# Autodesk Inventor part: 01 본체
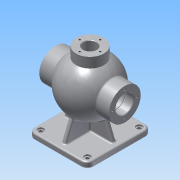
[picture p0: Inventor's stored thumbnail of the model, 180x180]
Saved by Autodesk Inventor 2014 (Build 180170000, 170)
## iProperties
Created: 2017-01
Part Number: 01 본체
Material: Aluminum 6061
Document SubType Name: Modeling
Designer: ksu
Density: 2.71 g/cm^3
Appearance: Aluminum - Flat
Author: ksu
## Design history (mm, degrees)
sketch "Sketch1"
  geometry: L1 (0, 0)-(20.642, 0); L2 (99.745, 0)-(136, 0); L3 (0, 0)-(136, 0); L4 (0, 0)-(136, 0); L5 (136, 0)-(136, 31); L6 (0, 31)-(0, 0); L7 (136, 31)-(110.741, 31); L8 (25.012, 31)-(0, 31); A1 r 53 centre (67.876, -0.171) between (110.741, 31) and (25.012, 31)
  constraints: 16 end point, 3 horizontal, 3 parallel, 2 point on circle, 1 centre point, 1 collinear, 1 perpendicular
  dimensions: "d2" = 136 distance between parallel lines of L6 L5; "d40" = 31 distance between parallel lines of L1 L8; "d41" = 31 distance between parallel lines of L2 L7
revolve "Revolution1" sketch "Sketch1" stored, may be unused: angle "d3" = 90 deg
workplane "Work Plane1"
sketch "Sketch2"
  geometry: L1 (0, 31)-(0, -31) reference; L2 (-136, 31)-(-136, -31) reference; L3 (-110.741, 31)-(-136, 31) reference; L4 (-22.5, 62.5)-(-113.5, 62.5); L5 (-125.5, 50.5)-(-125.5, -50.5); L6 (-113.5, -62.5)-(-22.5, -62.5); L7 (-10.5, -50.5)-(-10.5, 50.5); A1 r 12 centre (-22.5, 50.5) between (-10.5, 50.5) and (-22.5, 62.5); A2 r 12 centre (-22.5, -50.5) between (-22.5, -62.5) and (-10.5, -50.5); A3 r 12 centre (-113.5, -50.5) between (-125.5, -50.5) and (-113.5, -62.5); A4 r 12 centre (-113.5, 50.5) between (-113.5, 62.5) and (-125.5, 50.5); 4 further points
  constraints: 8 end point, 8 point on circle, 8 tangent, 6 point on line, 4 centre point, 3 equal radius, 2 parallel, 1 horizontal, 1 perpendicular
  dimensions: "d10" = 115 distance of point (-10.5, -62.5) point (-125.5, -62.5); "d11" = 125 distance of point (-125.5, -62.5) point (-125.5, 62.5); "d12" = 12 radius of A1
extrude "Extrusion1" join sketch "Sketch2" distance "d13" = 10; taper "d14" = 0 deg
sketch "Sketch3"
  geometry: A1 r 12 centre (113.5, -50.5) between (113.5, -62.5) and (125.5, -50.5) reference; A2 r 12 centre (113.5, 50.5) between (125.5, 50.5) and (113.5, 62.5) reference; A3 r 12 centre (22.5, 50.5) between (22.5, 62.5) and (10.5, 50.5) reference; A4 r 12 centre (22.5, -50.5) between (10.5, -50.5) and (22.5, -62.5) reference; 5 further points
  constraints: 4 coincident
hole "Hole1" sketch "Sketch3" at (22.5, -50.5), (22.5, 50.5), (113.5, 50.5), (113.5, -50.5) diameter "d15" = 8; stored, may be unused: countersink angle "d19" = 90 deg, drill point angle "d21" = 0 deg; dims "d16" = 6, "d17" = 12, "d18" = 3, "d20" = 10
workplane "Work Plane2"
workplane "Work Plane3"
workplane "Work Plane4"
sketch "Sketch11"
  geometry: L1 (0, -31)-(0, 31) reference; L2 (0, 31)-(25.012, 31) reference; L3 (110.741, 31)-(136, 31) reference; L4 (136, 31)-(136, -31) reference; L5 (136, -31)-(110.741, -31) reference; L6 (25.012, -31)-(0, -31) reference; L7 (10.5, -75)-(125.5, -75) reference; L8 (125.5, -75)-(125.5, -85) reference; L9 (125.5, -85)-(10.5, -85) reference; L10 (10.5, -85)-(10.5, -75) reference; L11 (0, 0)-(136, 0); L12 (136, 0)-(136, 17.5); L13 (0, 17.5)-(0, 0); L14 (28.523, 17.5)-(0, 17.5); L15 (120, 0)-(118.25, 0); L16 (118.25, 17.5)-(118.25, 18.5); L17 (118.25, 18.5)-(120, 18.5); L18 (120, 18.5)-(120, 17.5); L19 (136, 17.5)-(120, 17.5); L20 (118.25, 17.5)-(107.23, 17.5); A1 r 43 centre (67.876, 0.171) between (107.23, 17.5) and (28.523, 17.5); A2 r 53 centre (67.876, 0.171) between (25.012, -31) and (110.741, -31) reference; A3 r 53 centre (67.876, -0.171) between (110.741, 31) and (25.012, 31) reference
  constraints: 20 end point, 6 parallel, 2 horizontal, 2 perpendicular, 2 point on circle, 2 point on line, 1 centre point
  dimensions: "d75" = 86 diameter of A1; "d77" = 1.75 distance of L16.end L17.end; "d78" = 16 distance between parallel lines of L4 L18; "d79" = 18.5 distance of L17.end L15.start
revolve "Revolution2" sketch "Sketch11" stored, may be unused: angle "d80" = 90 deg
sketch "Sketch12"
  geometry: C1 r 17.5 at (0, 0) reference; 4 further points
  constraints: 5 other
  dimensions: "d81" = 24 distance of C1.centre point (0, 24); "d84" = 360 deg dimension on C1.centre point (0, 24) (derived)
hole "Hole2" sketch "Sketch12" at (0, 24), (-24, 0), (0, -24), (24, 0) diameter "d86" = 3.459; stored, may be unused: countersink angle "d90" = 90 deg, drill point angle "d92" = 118 deg; dims "d87" = 16, "d88" = 12, "d89" = 3, "d91" = 19
sketch "Sketch13"
  geometry: C1 r 17.5 at (0, 0) reference; 4 further points
  constraints: 5 other
  dimensions: "d93" = 22.5 distance of C1.centre point (0, 22.5); "d96" = 360 deg dimension on C1.centre point (0, 22.5) (derived)
hole "Hole3" sketch "Sketch13" at (0, 22.5), (-22.5, 0), (0, -22.5), (22.5, 0) diameter "d98" = 3.459; stored, may be unused: countersink angle "d102" = 90 deg, drill point angle "d104" = 118 deg; dims "d99" = 12, "d100" = 12, "d101" = 3, "d103" = 15
chamfer "Chamfer1" distance "d120" = 1; stored, may be unused: second distance "d121" = 2, angle "d122" = 45 deg
fillet "Fillet1" dims "d123" = 3
fillet "Fillet3" dims "d125" = 3
sketch "Sketch16"
  geometry: L1 (16.039, 22.5)-(15, 24.23) reference; L2 (0, 20.77)-(15, 20.77) reference; L3 (0, 24.23)-(0, 31) reference; L4 (0, 31)-(23.51, 31) reference; L5 (28.523, 17.5)-(1, 17.5) reference; L6 (1, 17.5)-(0, 18.5) reference; L7 (0, 18.5)-(0, 20.77) reference; L8 (15, 24.23)-(0, 24.23) reference; L9 (15, 20.77)-(16.039, 22.5) reference; L10 (117, -22.271)-(115.961, -24) reference; L11 (115.961, -24)-(117, -25.73) reference; L12 (117, -25.73)-(136, -25.73) reference; L13 (136, -25.73)-(136, -31) reference; L14 (136, -31)-(112.242, -31) reference; L15 (23.51, -31)-(0, -31) reference; L16 (0, -31)-(0, -24.23) reference; L17 (0, -24.23)-(15, -24.23) reference; L18 (15, -24.23)-(16.039, -22.5) reference; L19 (16.039, -22.5)-(15, -20.77) reference; L20 (15, -20.77)-(0, -20.77) reference; L21 (0, -20.77)-(0, -18.5) reference; L22 (0, -18.5)-(1, -17.5) reference; L23 (1, -17.5)-(28.523, -17.5) reference; L24 (107.23, -17.5)-(118.25, -17.5) reference; L25 (118.25, -17.5)-(118.25, -18.5) reference; L26 (118.25, -18.5)-(120, -18.5) reference; L27 (120, -18.5)-(120, -17.5) reference; L28 (120, -17.5)-(135, -17.5) reference; L29 (135, -17.5)-(136, -18.5) reference; L30 (136, -18.5)-(136, -22.271) reference; L31 (136, -22.271)-(117, -22.271) reference; L32 (117, 25.73)-(115.961, 24) reference; L33 (115.961, 24)-(117, 22.271) reference; L34 (117, 22.271)-(136, 22.271) reference; L35 (136, 22.271)-(136, 18.5) reference; L36 (136, 18.5)-(135, 17.5) reference; L37 (135, 17.5)-(120, 17.5) reference; L38 (120, 17.5)-(120, 18.5) reference; L39 (120, 18.5)-(118.25, 18.5) reference; L40 (118.25, 18.5)-(118.25, 17.5) reference; L41 (118.25, 17.5)-(107.23, 17.5) reference; L42 (112.242, 31)-(136, 31) reference; L43 (136, 31)-(136, 25.73) reference; L44 (136, 25.73)-(117, 25.73) reference; L45 (125.5, -78)-(125.5, -85) reference; L46 (125.5, -85)-(10.5, -85) reference; L47 (10.5, -85)-(10.5, -78) reference; L48 (13.5, -75)-(122.5, -75) reference; L49 (20.5, -75)-(36.603, -35.143); L50 (115.5, -75)-(99.331, -34.98); L51 (115.5, -75)-(20.5, -75); A1 r 3 centre (23.51, 34) between (23.51, 31) and (25.887, 32.169) reference; A2 r 43 centre (67.876, 0.171) between (107.23, 17.5) and (28.523, 17.5) reference; A3 r 3 centre (112.242, -34) between (112.242, -31) and (109.866, -32.169) reference; A4 r 53 centre (67.876, 0.171) between (25.887, -32.169) and (109.866, -32.169) reference; A5 r 3 centre (23.51, -34) between (25.887, -32.169) and (23.51, -31) reference; A6 r 43 centre (67.876, -0.171) between (28.523, -17.5) and (107.23, -17.5) reference; A7 r 3 centre (112.242, 34) between (109.866, 32.169) and (112.242, 31) reference; A8 r 3 centre (122.5, -78) between (125.5, -78) and (122.5, -75) reference; A9 r 3 centre (13.5, -78) between (13.5, -75) and (10.5, -78) reference; A10 r 46.916 centre (67.876, -0.171) between (36.603, -35.143) and (99.331, -34.98); A11 r 53 centre (67.876, -0.171) between (109.866, 32.169) and (25.887, 32.169) reference; 1 further point
  constraints: 6 end point, 2 point on circle, 2 point on line, 1 centre point, 1 collinear
  dimensions: "d126" = 22 deg angle of L47 L49; "d127" = 22 deg angle of L45 L50; "d128" = 10 distance from line of L45 L50.start; "d129" = 10 distance from line of L47 L49.start
extrude "Extrusion7" join sketch "Sketch16" distance "d130" = 4; taper "d132" = 0 deg; dims "d131" = 4, "d133" = 0
workplane "Work Plane5"
sketch "Sketch17"
  geometry: L1 (-52.677, -4)-(-75, -4) reference; L2 (-75, -4)-(-75, -59.5) reference; L3 (-78, -62.5)-(-85, -62.5) reference; L4 (-85, -62.5)-(-85, 62.5) reference; L5 (-85, 62.5)-(-78, 62.5) reference; L6 (-75, 59.5)-(-75, 4) reference; L7 (-75, 4)-(-52.677, 4) reference; L8 (-75, 52.5)-(-32.266, 35.234); L9 (-75, -52.5)-(-32.266, -35.234); L10 (-75, 52.5)-(-75, -52.5); C1 r 43.171 at (0, 0) reference; A1 r 3 centre (-78, -59.5) between (-78, -62.5) and (-75, -59.5) reference; A2 r 3 centre (-78, 59.5) between (-75, 59.5) and (-78, 62.5) reference; A3 r 47.776 centre (0, 0) between (-32.266, 35.234) and (-32.266, -35.234); A4 r 52.829 centre (0, 0) between (-52.677, -4) and (-52.677, 4) reference; 1 further point
  constraints: 6 end point, 2 point on circle, 2 point on line, 1 centre point, 1 coincident
  dimensions: "d135" = 22 deg angle of L9 L3; "d136" = 10 distance from line of L3 L9.start; "d137" = 22 deg angle of L5 L8; "d138" = 10 distance from line of L5 L8.start
extrude "Extrusion8" join sketch "Sketch17" distance "d139" = 4; taper "d141" = 0 deg; dims "d140" = 4, "d142" = 0
fillet "Fillet4" dims "d143" = 3
workplane "Work Plane6"
workplane "Work Plane7"
sketch "Sketch19"
  geometry: L1 (40.876, 65)-(94.876, 65) reference; L2 (40.876, 65)-(40.876, 47.115) reference; L3 (-88.616, 58.002)-(224.368, 58.002); L4 (224.368, 58.002)-(224.368, 51.998); L5 (224.368, 51.998)-(-88.616, 51.998); L6 (-88.616, 51.998)-(-88.616, 58.002); L7 (224.368, 55)-(-88.616, 55); L8 (67.876, 58.002)-(67.876, 51.998); 1 further point
  constraints: 4 end point, 4 midpoint, 2 other
  dimensions: "d148" = 27 distance between parallel lines of L2 L8; "d149" = 10 distance between parallel lines of L1 L7
emboss "Emboss1" sketch "Sketch19" dims "d10" = 115, "d11" = 125, "d12" = 12, "d150" = 0.5, "d151" = 0
workplane "Work Plane8"
sketch "Sketch20"
  geometry: L1 (-136, 31)-(-136, -31) reference; L2 (0, 31)-(0, -31) reference; L3 (-136, 0)-(0, 0); C1 r 27 at (-68, 0)
  constraints: 2 end point, 2 midpoint, 1 centre point, 1 perpendicular
  dimensions: "d153" = 54 diameter of C1
extrude "Extrusion9" join sketch "Sketch20" distance "d154" = 25; taper "d155" = 0 deg
sketch "Sketch21"
  geometry: C1 r 27 at (0, 0) reference; C2 r 13 at (0, 0); 1 further point
  constraints: 1 centre point, 1 coincident
  dimensions: "d156" = 26 diameter of C2
extrude "Extrusion10" cut sketch "Sketch21" distance "d157" = 30; taper "d158" = 0 deg
sketch "Sketch22"
  geometry: C1 r 13 at (0, 0) reference; 5 further points
  constraints: 5 other
  dimensions: "d159" = 20 distance of C1.centre point (0, 20); "d162" = 360 deg dimension on C1.centre point (0, 20) (derived)
hole "Hole5" sketch "Sketch22" at (0, 20), (-20, 0), (0, -20), (20, 0) diameter "d164" = 3.459; stored, may be unused: countersink angle "d168" = 90 deg, drill point angle "d170" = 118 deg; dims "d165" = 9, "d166" = 12, "d167" = 3, "d169" = 11
workplane "Work Plane9"
sketch "Sketch23"
  geometry: L1 (-95, 65)-(-41, 65) reference; L2 (-95, 65)-(-95, 45.363) reference; L3 (-87.247, 58.002)-(-48.753, 58.002); L4 (-48.753, 58.002)-(-48.753, 51.998); L5 (-48.753, 51.998)-(-87.247, 51.998); L6 (-87.247, 51.998)-(-87.247, 58.002); L7 (-87.247, 55)-(-48.753, 55); L8 (-68, 58.002)-(-68, 51.998); 1 further point
  constraints: 4 end point, 4 midpoint, 2 other
  dimensions: "d172" = 10 distance between parallel lines of L1 L7; "d173" = 27 distance between parallel lines of L2 L8
emboss "Emboss2" sketch "Sketch23" dims "d10" = 115, "d11" = 125, "d12" = 12, "d174" = 0.5, "d175" = 0
chamfer "Chamfer2" distance "d176" = 1; stored, may be unused: second distance "d177" = 2, angle "d178" = 45 deg
body "Solid1"
node "Project Cut Edges7"
node "Project Cut Edges8"
node "Project Cut Edges9"
other parameters: "d4" = -85, "d22" = 68, "d42" = 68, "d71" = 65, "d76" = 17.5, "d134" = 68, "d144" = -27, "d147" = 27, "d152" = 65, "d171" = -27
